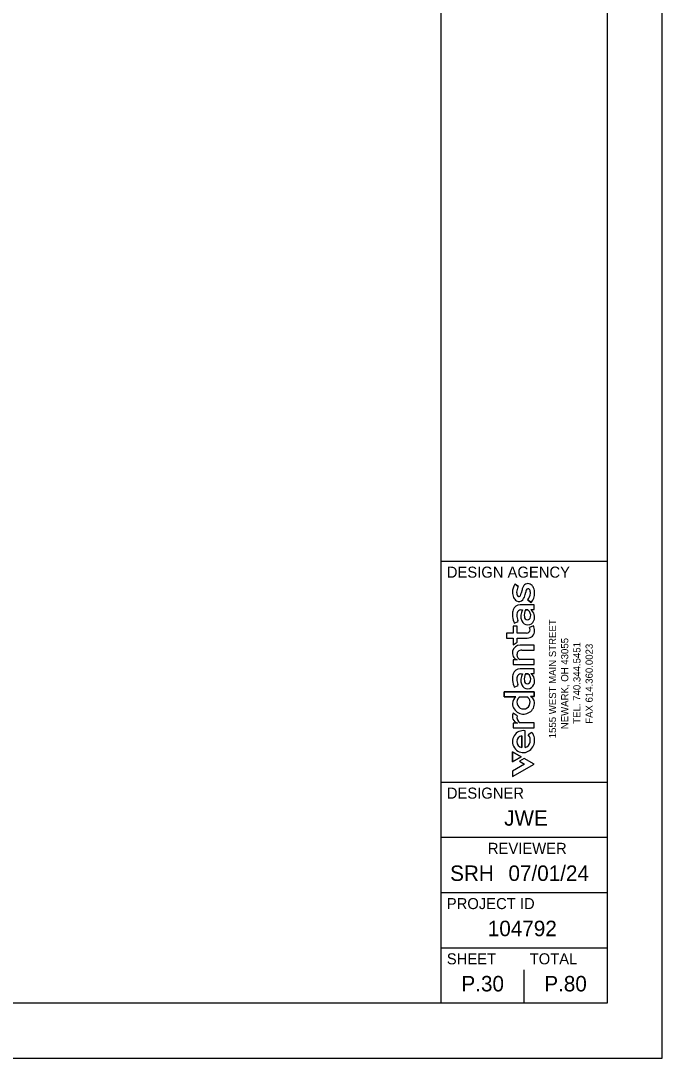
# Model space of a CAD drawing. Extents: x 0 to 37.7, y 0 to 22.
# Drawn here: x 28.19 to 34, y 0 to 9.39 of the extents above; entities that cross this region are included whole.
import ezdxf

# ---------------------------------------------------------------- set-up
doc = ezdxf.new("R2010")
doc.units = 0
for name, color, linetype in [('SH_Border', 7, 'Continuous'), ('SH_Cut_Line', 7, 'Continuous'), ('SH_Data', 7, 'Continuous'), ('SH_Text', 7, 'Continuous')]:
    doc.layers.add(name, color=color, linetype=linetype)

msp = doc.modelspace()

# ---------------------------------------------------------------- linework, layer by layer
at = {"layer": 'SH_Border'}
for p, q in [((32, 0.5), (32, 21.5)), ((32, 4.5), (33.5, 4.5)), ((32, 2.5), (33.5, 2.5)), ((32, 2), (33.5, 2)), ((32, 1.5), (33.5, 1.5)), ((32, 1), (33.5, 1))]:
    msp.add_line(p, q, dxfattribs=at)
msp.add_lwpolyline([(1.5, 21.5), (33.5, 21.5), (33.5, 0.5), (1.5, 0.5)], close=True, dxfattribs=at)
at = {"layer": 'SH_Cut_Line'}
msp.add_lwpolyline([(0, 0), (34, 0), (34, 22), (0, 22)], close=True, dxfattribs=at)
at = {"layer": 'SH_Data'}
for p, q in [((32.75, 3.5), (32.75, 3.5)), ((32.75, 0.5), (32.75, 0.8)), ((32.375, 0.675), (32.375, 0.675))]:
    msp.add_line(p, q, dxfattribs=at)
at = {"layer": 'SH_Text'}
for p, q in [((32.6962, 4.2662), (32.6652, 4.2898)), ((32.7306, 4.2404), (32.7239, 4.2093)), ((32.7598, 4.1986), (32.7641, 4.2186)), ((32.7824, 4.1507), (32.8151, 4.1269)), ((32.7198, 4.0581), (32.7358, 4.0581)), ((32.7613, 4.0581), (32.7843, 4.0581)), ((32.656, 3.9502), (32.6608, 3.9382)), ((32.8335, 3.9145), (32.7983, 3.8982)), ((32.7198, 3.4796), (32.7358, 3.4796)), ((32.7613, 3.4796), (32.7843, 3.4796)), ((32.656, 3.3717), (32.6608, 3.3597)), ((32.7143, 3.2714), (32.7746, 3.2714)), ((32.6871, 3.1001), (32.6501, 3.1224)), ((32.7291, 2.9195), (32.7291, 2.8123)), ((32.7594, 2.8114), (32.7594, 2.9645)), ((32.8188, 2.9498), (32.7865, 2.9276))]:
    msp.add_line(p, q, dxfattribs=at)
for points in [[(32.6979, 4.2688), (32.6661, 4.2911), (32.6652, 4.2898)], [(32.6962, 4.2662), (32.6979, 4.2688)], [(32.7306, 4.2404), (32.7239, 4.2093)], [(32.7598, 4.1986), (32.7641, 4.2186)], [(32.7824, 4.1507), (32.7801, 4.1482), (32.8116, 4.1232), (32.8151, 4.1269)], [(32.8096, 4.062), (32.8397, 4.062), (32.8397, 4.1036), (32.7146, 4.1036)], [(32.8096, 4.062), (32.8397, 4.062), (32.8397, 4.1036), (32.7146, 4.1036)], [(32.7198, 4.0581), (32.7358, 4.0581)], [(32.7843, 4.0581), (32.7613, 4.0581)], [(32.656, 3.9502), (32.6608, 3.9382)], [(32.6608, 3.9382), (32.6964, 3.9527), (32.6927, 3.9621)], [(32.6608, 3.9382), (32.6964, 3.9527), (32.6927, 3.9621)], [(32.77, 3.8488), (32.6881, 3.8488), (32.6881, 3.9098), (32.6492, 3.9098), (32.6492, 3.8488), (32.5909, 3.8488), (32.5909, 3.8033), (32.6492, 3.8033), (32.6492, 3.7436), (32.6882, 3.767), (32.6882, 3.8033), (32.778, 3.8033)], [(32.77, 3.8488), (32.6881, 3.8488), (32.6881, 3.9098), (32.6492, 3.9098), (32.6492, 3.8488), (32.5909, 3.8488), (32.5909, 3.8033), (32.6492, 3.8033), (32.6492, 3.7436), (32.6882, 3.767), (32.6882, 3.8033), (32.778, 3.8033)], [(32.8335, 3.9145), (32.7983, 3.8982)], [(32.728, 3.6945), (32.8397, 3.6945), (32.8397, 3.7399), (32.7153, 3.7399)], [(32.728, 3.6945), (32.8397, 3.6945), (32.8397, 3.7399), (32.7153, 3.7399)], [(32.6865, 3.605), (32.6492, 3.605), (32.6492, 3.563), (32.8397, 3.563), (32.8397, 3.6084), (32.7123, 3.6084)], [(32.6865, 3.605), (32.6492, 3.605), (32.6492, 3.563), (32.8397, 3.563), (32.8397, 3.6084), (32.7123, 3.6084)], [(32.8096, 3.4835), (32.8397, 3.4835), (32.8397, 3.5251), (32.7146, 3.5251)], [(32.8096, 3.4835), (32.8397, 3.4835), (32.8397, 3.5251), (32.7146, 3.5251)], [(32.7198, 3.4796), (32.7358, 3.4796)], [(32.7843, 3.4796), (32.7613, 3.4796)], [(32.6608, 3.3597), (32.6964, 3.3742), (32.6927, 3.3836)], [(32.6608, 3.3597), (32.6964, 3.3742), (32.6927, 3.3836)], [(32.6754, 3.2714), (32.5684, 3.2714), (32.5684, 3.3168), (32.8397, 3.3168), (32.8396, 3.2752), (32.8061, 3.2752)], [(32.8061, 3.2752), (32.8396, 3.2752), (32.8397, 3.3168), (32.5684, 3.3168), (32.5684, 3.2714), (32.6754, 3.2714)], [(32.656, 3.3717), (32.6608, 3.3597)], [(32.7143, 3.2714), (32.7746, 3.2714)], [(32.6871, 3.1001), (32.6501, 3.1224)], [(32.6899, 3.0328), (32.6491, 3.0328), (32.6491, 2.9914), (32.8396, 2.9914), (32.8396, 3.0353), (32.7134, 3.0353)], [(32.6899, 3.0328), (32.6491, 3.0328), (32.6491, 2.9914), (32.8396, 2.9914), (32.8396, 3.0353), (32.7134, 3.0353)], [(32.7291, 2.8123), (32.7291, 2.9195)], [(32.7594, 2.8114), (32.7594, 2.9645)], [(32.8188, 2.9498), (32.7865, 2.9276)], [(32.6441, 2.7746), (32.6441, 2.6838), (32.7228, 2.7292), (32.6441, 2.7746)], [(32.7081, 2.6876), (32.7526, 2.6619), (32.6441, 2.5992), (32.6441, 2.5492), (32.8394, 2.6619), (32.7514, 2.7127), (32.7081, 2.6876)]]:
    msp.add_lwpolyline(points, dxfattribs=at)
for points in [[(32.7228, 2.7292), (32.6441, 2.6838), (32.6441, 2.7746)], [(32.7081, 2.6876), (32.7526, 2.6619), (32.6441, 2.5992), (32.6441, 2.5492), (32.8394, 2.6619), (32.7514, 2.7127)]]:
    msp.add_lwpolyline(points, close=True, dxfattribs=at)
for centre, radius, start, end in [((32.7755, 4.2188), 0.1313, 147.22328, 179.84204), ((32.7755, 4.2188), 0.1313, 147.22328, 179.84204), ((32.7768, 4.2161), 0.0948, 148.12326, 178.11353), ((32.7768, 4.2161), 0.0948, 148.12326, 178.11353), ((32.8571, 4.2117), 0.1296, 154.04469, 167.21491), ((32.8571, 4.2117), 0.1296, 154.04469, 167.21491), ((32.7848, 4.2471), 0.0493, 52.70919, 154.21664), ((32.7848, 4.2471), 0.0493, 52.70919, 154.21664), ((32.8578, 4.2031), 0.0949, 158.18628, 170.63281), ((32.8578, 4.2031), 0.0949, 158.18628, 170.63281), ((32.7855, 4.2337), 0.0165, 26.91646, 163.60196), ((32.7855, 4.2337), 0.0165, 26.91646, 163.60196), ((32.7416, 4.2122), 0.0655, 357.00773, 26.31116), ((32.7416, 4.2122), 0.0655, 357.00773, 26.31116), ((32.7697, 4.2312), 0.0711, 22.82777, 50.71565), ((32.7697, 4.2312), 0.0711, 22.82777, 50.71565), ((32.725, 4.2122), 0.1196, 359.0192, 22.9257), ((32.725, 4.2122), 0.1196, 359.0192, 22.9257), ((32.7581, 4.2172), 0.1139, 179.01095, 203.55998), ((32.7581, 4.2172), 0.1139, 179.01095, 203.55998), ((32.7152, 4.1982), 0.067, 203.36923, 237.807), ((32.7152, 4.1982), 0.067, 203.36923, 237.807), ((32.7032, 4.1808), 0.0458, 238.94525, 317.68291), ((32.7032, 4.1808), 0.0458, 238.94525, 317.68291), ((32.7521, 4.2181), 0.0702, 179.05393, 195.69208), ((32.7521, 4.2181), 0.0702, 179.05393, 195.69208), ((32.7171, 4.2071), 0.0335, 193.85614, 223.71908), ((32.7171, 4.2071), 0.0335, 193.85614, 223.71908), ((32.7034, 4.1944), 0.0148, 224.78223, 330.43657), ((32.7034, 4.1944), 0.0148, 224.78223, 330.43657), ((32.6434, 4.2244), 0.0819, 332.90022, 349.38313), ((32.6434, 4.2244), 0.0819, 332.90022, 349.38313), ((32.6563, 4.2174), 0.1053, 320.12588, 349.70225), ((32.6563, 4.2174), 0.1053, 320.12588, 349.70225), ((32.7139, 4.2138), 0.0932, 317.36304, 356.92436), ((32.7139, 4.2138), 0.0932, 317.36304, 356.92436), ((32.7152, 4.2092), 0.1295, 320.51657, 0.43409), ((32.7152, 4.2092), 0.1295, 320.51657, 0.43409), ((32.7725, 4.0164), 0.1283, 160.81276, 180.93166), ((32.7725, 4.0164), 0.1283, 160.81276, 180.93166), ((32.7124, 4.0397), 0.0639, 88.07599, 162.86424), ((32.7124, 4.0397), 0.0639, 88.07599, 162.86424), ((32.7217, 4.0208), 0.0374, 92.96709, 165.223), ((32.7217, 4.0208), 0.0374, 92.96709, 165.223), ((32.8282, 4.0012), 0.1085, 148.34975, 202.47075), ((32.8282, 4.0012), 0.1085, 148.34975, 202.47075), ((32.8554, 4.0119), 0.1048, 153.83718, 188.87457), ((32.8554, 4.0119), 0.1048, 153.83718, 188.87457), ((32.7455, 4.0077), 0.0637, 348.12474, 52.36783), ((32.7455, 4.0077), 0.0637, 348.12474, 52.36783), ((32.7589, 3.9928), 0.0857, 338.27739, 53.79489), ((32.7589, 3.9928), 0.0857, 338.27739, 53.79489), ((32.8428, 4.0176), 0.1986, 180.9467, 199.83537), ((32.8428, 4.0176), 0.1986, 180.9467, 199.83537), ((32.7475, 4.0117), 0.0647, 163.25224, 179.99706), ((32.7475, 4.0117), 0.0647, 163.25224, 179.99706), ((32.8343, 4.0161), 0.1516, 181.66161, 200.87137), ((32.8343, 4.0161), 0.1516, 181.66161, 200.87137), ((32.783, 3.9816), 0.0592, 201.67635, 339.72677), ((32.783, 3.9816), 0.0592, 201.67635, 339.72677), ((32.7798, 3.9969), 0.0281, 182.32704, 355.37776), ((32.7798, 3.9969), 0.0281, 182.32704, 355.37776), ((32.7727, 3.8801), 0.0314, 265.06923, 356.35481), ((32.7727, 3.8801), 0.0314, 265.06923, 356.35481), ((32.7804, 3.8675), 0.0642, 267.86409, 1.62134), ((32.7804, 3.8675), 0.0642, 267.86409, 1.62134), ((32.7609, 3.8767), 0.0432, 1.86376, 29.96515), ((32.7609, 3.8767), 0.0432, 1.86376, 29.96515), ((32.7508, 3.8701), 0.0939, 359.5424, 28.24947), ((32.7508, 3.8701), 0.0939, 359.5424, 28.24947), ((32.7141, 3.6697), 0.0703, 88.98961, 246.91113), ((32.7141, 3.6697), 0.0703, 88.98961, 246.91113), ((32.7282, 3.6536), 0.0434, 137.30492, 182.96879), ((32.7282, 3.6536), 0.0434, 137.30492, 182.96879), ((32.7257, 3.6512), 0.0433, 86.97388, 132.7421), ((32.7257, 3.6512), 0.0433, 86.97388, 132.7421), ((32.7326, 3.6516), 0.0477, 180.34657, 244.91134), ((32.7326, 3.6516), 0.0477, 180.34657, 244.91134), ((32.7725, 3.4379), 0.1283, 160.81276, 180.93166), ((32.7725, 3.4379), 0.1283, 160.81276, 180.93166), ((32.7124, 3.4612), 0.0639, 88.07599, 162.86424), ((32.7124, 3.4612), 0.0639, 88.07599, 162.86424), ((32.7217, 3.4423), 0.0374, 92.96709, 165.223), ((32.7217, 3.4423), 0.0374, 92.96709, 165.223), ((32.8282, 3.4227), 0.1085, 148.34975, 202.47075), ((32.8282, 3.4227), 0.1085, 148.34975, 202.47075), ((32.8554, 3.4334), 0.1048, 153.83718, 188.87457), ((32.8554, 3.4334), 0.1048, 153.83718, 188.87457), ((32.7455, 3.4292), 0.0637, 348.12474, 52.36783), ((32.7455, 3.4292), 0.0637, 348.12474, 52.36783), ((32.7589, 3.4143), 0.0857, 338.27739, 53.79489), ((32.7589, 3.4143), 0.0857, 338.27739, 53.79489), ((32.8428, 3.4391), 0.1986, 180.9467, 199.83537), ((32.8428, 3.4391), 0.1986, 180.9467, 199.83537), ((32.7475, 3.4332), 0.0647, 163.25224, 179.99706), ((32.7475, 3.4332), 0.0647, 163.25224, 179.99706), ((32.8343, 3.4376), 0.1516, 181.66161, 200.87137), ((32.8343, 3.4376), 0.1516, 181.66161, 200.87137), ((32.783, 3.4031), 0.0592, 201.67635, 339.72677), ((32.783, 3.4031), 0.0592, 201.67635, 339.72677), ((32.7798, 3.4184), 0.0281, 182.32704, 355.37776), ((32.7798, 3.4184), 0.0281, 182.32704, 355.37776), ((32.7156, 3.2124), 0.0714, 124.28433, 181.27226), ((32.7156, 3.2124), 0.0714, 124.28433, 181.27226), ((32.7442, 3.2156), 0.1001, 182.77189, 2.9779), ((32.7442, 3.2156), 0.1001, 182.77189, 2.9779), ((32.7444, 3.2214), 0.0595, 176.4529, 5.05495), ((32.7444, 3.2214), 0.0595, 176.4529, 5.05495), ((32.7435, 3.2206), 0.0586, 119.90067, 175.57974), ((32.7435, 3.2206), 0.0586, 119.90067, 175.57974), ((32.7452, 3.2204), 0.0588, 6.06662, 60.04101), ((32.7452, 3.2204), 0.0588, 6.06662, 60.04101), ((32.7773, 3.2146), 0.0671, 5.30838, 64.52521), ((32.7773, 3.2146), 0.0671, 5.30838, 64.52521), ((32.7059, 3.0936), 0.0628, 152.6524, 255.29294), ((32.7059, 3.0936), 0.0628, 152.6524, 255.29294), ((32.7389, 3.0834), 0.0545, 162.13838, 242.04081), ((32.7389, 3.0834), 0.0545, 162.13838, 242.04081), ((32.7439, 2.8661), 0.0996, 81.04458, 280.25771), ((32.7439, 2.8661), 0.0996, 81.04458, 280.25771), ((32.7374, 2.8659), 0.0543, 98.83779, 261.16221), ((32.7374, 2.8659), 0.0543, 98.83779, 261.16221), ((32.7337, 2.8787), 0.072, 290.92317, 42.73906), ((32.7337, 2.8787), 0.072, 290.92317, 42.73906), ((32.7309, 2.8776), 0.1138, 285.66678, 39.36993), ((32.7309, 2.8776), 0.1138, 285.66678, 39.36993)]:
    msp.add_arc(centre, radius, start, end, dxfattribs=at)

# ---------------------------------------------------------------- texts
at = {"layer": 'SH_Data'}
for s, height, p in [('DESIGN AGENCY', 0.1, (32.05, 4.35)), ('DESIGNER', 0.1, (32.05, 2.35)), ('JWE', 0.14, (32.5687, 2.105)), ('REVIEWER', 0.1, (32.4218, 1.85)), ('SRH', 0.14, (32.08, 1.605)), ('07/01/24', 0.14, (32.6078, 1.605)), ('PROJECT ID', 0.1, (32.05, 1.35)), ('104792', 0.14, (32.4209, 1.105)), ('SHEET', 0.1, (32.05, 0.85)), ('TOTAL', 0.1, (32.8, 0.85)), ('P.30', 0.14, (32.1822, 0.605)), ('P.80', 0.14, (32.9322, 0.605))]:
    msp.add_text(s, height=height, dxfattribs=at).set_placement(p)
at = {"layer": 'SH_Text'}
for s, p in [('1555 WEST MAIN STREET', (33.039, 2.8964)), ('NEWARK, OH 43055', (33.1495, 2.9783)), ('TEL. 740.344.5451', (33.2599, 3.028)), ('FAX 614.360.0023', (33.3705, 3.0274))]:
    msp.add_text(s, height=0.064969, rotation=90, dxfattribs=at).set_placement(p)

doc.saveas('drawing.dxf')
